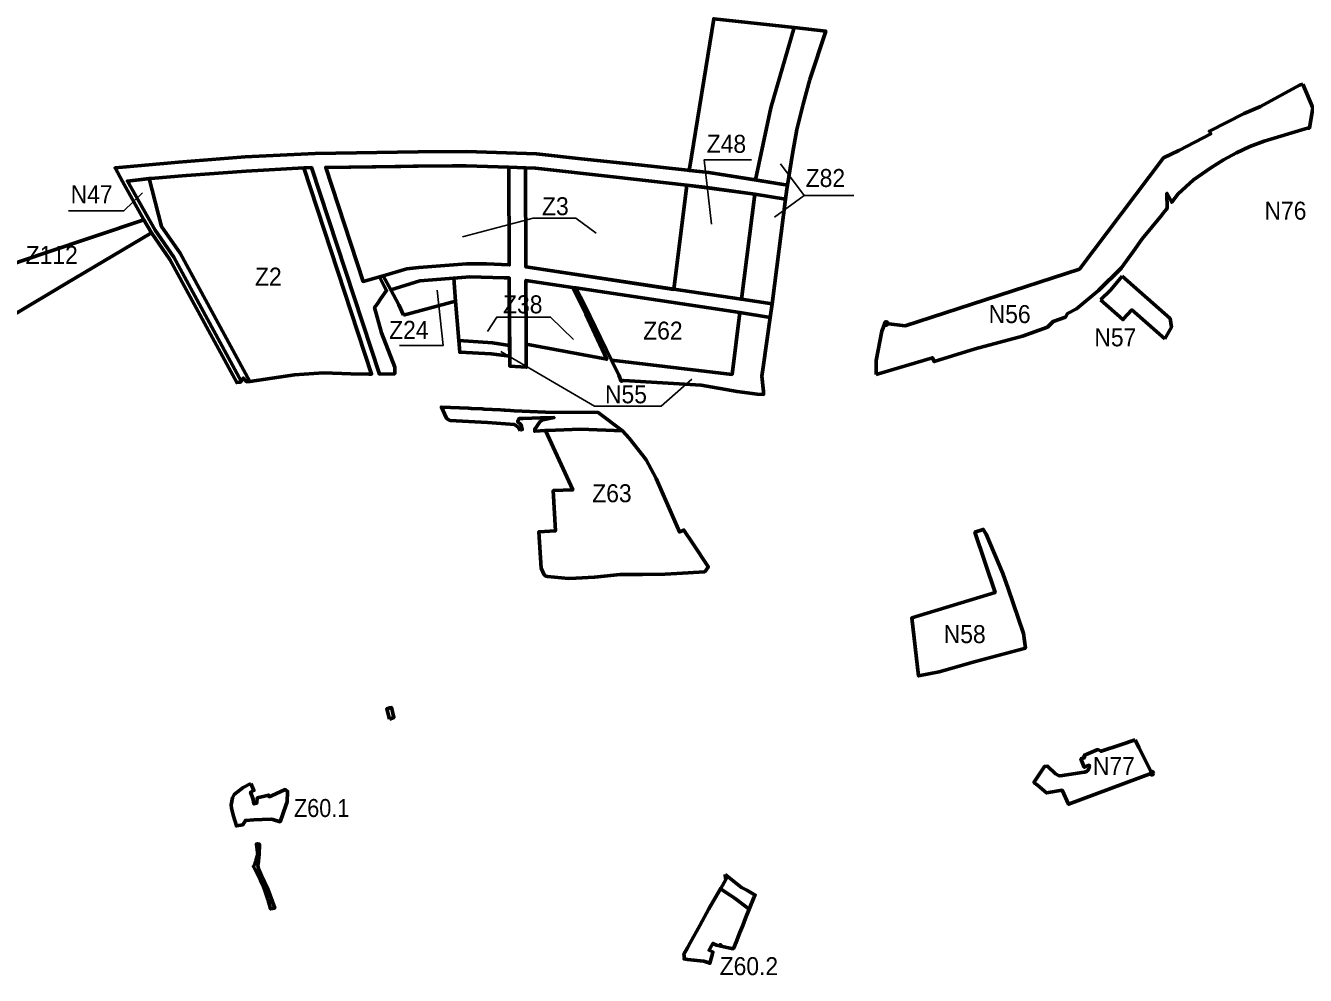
# Model space of a CAD drawing. Extents: x -650277 to -643422, y -1073980 to -1066720.
# Drawn here: x -647728 to -646020, y -1070629 to -1069362 of the extents above; entities that cross this region are included whole.
import ezdxf

# ---------------------------------------------------------------- set-up
doc = ezdxf.new("R2010")
doc.units = 0
doc.header["$LTSCALE"] = 9.6
doc.header["$PDMODE"] = 32
doc.header["$PDSIZE"] = 4.8
for name, color, linetype, lineweight in [('1', 7, 'Continuous', 60), ('13', 7, 'Continuous', 60), ('15', 7, 'Continuous', 60), ('17', 7, 'Continuous', 60), ('18', 7, 'Continuous', 60), ('35', 7, 'Continuous', 60), ('42', 7, 'Continuous', 60), ('48', 7, 'Continuous', 60), ('59', 7, 'Continuous', 25), ('60', 7, 'Continuous', 60), ('63', 7, 'Continuous', 25), ('9', 7, 'Continuous', 60)]:
    doc.layers.add(name, color=color, linetype=linetype, lineweight=lineweight)

msp = doc.modelspace()

# ---------------------------------------------------------------- linework, layer by layer
at = {"layer": '1'}
for points in [[(-647356.899, -1069552.034), (-647433.779, -1069556.106), (-647433.779, -1069556.106), (-647513.66, -1069562.249), (-647514.067, -1069562.282), (-647560.836, -1069566.036), (-647563.104, -1069566.28)], [(-647369.3, -1069828.22), (-647330.46, -1069825.51), (-647294.38, -1069826.88), (-647270.09, -1069827.02), (-647266.581, -1069827.042), (-647356.899, -1069552.034)], [(-647563.104, -1069566.28), (-647546.777, -1069629.901), (-647521.943, -1069665.763)], [(-647521.943, -1069665.763), (-647428.993, -1069836.714), (-647369.3, -1069828.22)]]:
    msp.add_lwpolyline(points, dxfattribs=at)
for points in [[(-647251.002, -1069695.852), (-647219.628, -1069686.746), (-647203.374, -1069684.716), (-647139.649, -1069679.961), (-647113.255, -1069679.966), (-647082.761, -1069681.399), (-647083.356, -1069551.018), (-647140.247, -1069549.071), (-647158.572, -1069549.252), (-647211.05, -1069549.77), (-647227.623, -1069550.23), (-647327.682, -1069551.263), (-647277.71, -1069703.421)], [(-646944.168, -1069563.743), (-647047.648, -1069552.245), (-647061.304, -1069551.773), (-647060.7, -1069683.894), (-646863, -1069714), (-646846, -1069575)], [(-647223.66, -1069748.26), (-647154.33, -1069729.69), (-647156.782, -1069698.901), (-647202.181, -1069702.678), (-647240.994, -1069714.513), (-647230.16, -1069734.42)], [(-647150.138, -1069782.334), (-647105.334, -1069785.168), (-647082.271, -1069788.81), (-647082.682, -1069698.791), (-647089.456, -1069698.579), (-647135.585, -1069697.137), (-647156.782, -1069698.901), (-647154.33, -1069729.69)], [(-647060.23, -1069786.932), (-646952.56, -1069807.13), (-646980.4, -1069746.98), (-646998.56, -1069711.443), (-647060.617, -1069702.116)]]:
    msp.add_lwpolyline(points, close=True, dxfattribs=at)
at = {"layer": '13'}
msp.add_line((-646733.74, -1069471.688), (-646702.425, -1069364.771), dxfattribs=at)
msp.add_lwpolyline([(-646702.425, -1069364.771), (-646809.879, -1069353.002), (-646842.103, -1069553.182), (-646842.441, -1069555.283), (-646816.615, -1069558.064), (-646754.066, -1069567.993), (-646733.74, -1069471.688)], dxfattribs=at)
msp.add_lwpolyline([(-646842.148, -1069716.763), (-646772.906, -1069727.176), (-646755.269, -1069587.04), (-646846, -1069575), (-646862.955, -1069713.634)], close=True, dxfattribs=at)
at = {"layer": '15'}
for points in [[(-647433.779, -1069556.106), (-647356.899, -1069552.034), (-647346.554, -1069551.486), (-647256.034, -1069827.107), (-647235.49, -1069826.51), (-647235.62, -1069817.62), (-647253.45, -1069771.95), (-647262.46, -1069738.25), (-647259.11, -1069733.52), (-647253.97, -1069726.27), (-647246.42, -1069715.63), (-647249.555, -1069709.677), (-647256.061, -1069697.32), (-647277.71, -1069703.421), (-647327.682, -1069551.263), (-647204.208, -1069549.647), (-647140.247, -1069549.071), (-647083.356, -1069551.018), (-647061.304, -1069551.773), (-647047.702, -1069552.239), (-646944.167, -1069563.743), (-646822.169, -1069577.72), (-646755.269, -1069587.04), (-646714.037, -1069593.585), (-646712.34, -1069580.49), (-646711.444, -1069574.771), (-646711.442, -1069574.759), (-646816.615, -1069558.064), (-646910.029, -1069548.006), (-646986.633, -1069539.757), (-647046.325, -1069533.275), (-647140.008, -1069530.068), (-647204.293, -1069530.647), (-647341.697, -1069532.602), (-647434.969, -1069537.141), (-647523.931, -1069544.499), (-647568.792, -1069548.21), (-647608.81, -1069551.868), (-647598.735, -1069570.026), (-647573.15, -1069616.16), (-647570.37, -1069621.18), (-647560.36, -1069638.39), (-647535.588, -1069674.163), (-647446.322, -1069838.338), (-647441.19, -1069837.6), (-647440.46, -1069836.558), (-647530.471, -1069671.013), (-647555.266, -1069635.207), (-647592.199, -1069569.411), (-647560.836, -1069566.036), (-647514.067, -1069562.282), (-647513.66, -1069562.249), (-647433.779, -1069556.106)], [(-647242.698, -1070287.238), (-647236.567, -1070285.154), (-647239.781, -1070272.031), (-647242.06, -1070272.35), (-647246.28, -1070273.733)], [(-647404.96, -1070527.57), (-647401.35, -1070540.59), (-647395.75, -1070539.47), (-647404.879, -1070514.114), (-647413.552, -1070496.671), (-647417.297, -1070487.185), (-647418.038, -1070482.516), (-647417.482, -1070476.846), (-647416.37, -1070468.064), (-647416.148, -1070454.055), (-647418.49, -1070453.76), (-647420.13, -1070454.78), (-647420.22, -1070454.02), (-647418.41, -1070468.21), (-647420.74, -1070476.57), (-647422.285, -1070480.931), (-647424.226, -1070484.029), (-647422.19, -1070487.75), (-647414.6, -1070502.16), (-647410.86, -1070510.68), (-647408.82, -1070515.49)]]:
    msp.add_lwpolyline(points, close=True, dxfattribs=at)
for points in [[(-647083.356, -1069551.018), (-647082.761, -1069681.399), (-647113.255, -1069679.966), (-647139.649, -1069679.961), (-647203.374, -1069684.716), (-647219.628, -1069686.746), (-647251.002, -1069695.852), (-647240.994, -1069714.513), (-647202.181, -1069702.678), (-647135.585, -1069697.137), (-647089.456, -1069698.579), (-647082.682, -1069698.791), (-647082.206, -1069802.916)], [(-647060.617, -1069702.116), (-646998.56, -1069711.443), (-646993.771, -1069712.163), (-646775.286, -1069745.022), (-646734.48, -1069751.35), (-646732.143, -1069733.308), (-646772.906, -1069727.176), (-646842.148, -1069716.763), (-647060.7, -1069683.894), (-647061.304, -1069551.773), (-647083.356, -1069551.018)], [(-647082.206, -1069802.916), (-647082.145, -1069816.321), (-647060.029, -1069817.854), (-647060.23, -1069786.932), (-647060.617, -1069702.116)], [(-646931.67, -1069902.89), (-646964.111, -1069878.315), (-647034.195, -1069877.629), (-647076, -1069875.85), (-647081.25, -1069875.56), (-647081.26, -1069875.76), (-647088.94, -1069875.34), (-647088.93, -1069875.14), (-647094.24, -1069874.85), (-647116.31, -1069873.65), (-647118.77, -1069873.51), (-647133.58, -1069872.73), (-647136.94, -1069872.55), (-647173.23, -1069871.09), (-647167.14, -1069884.85)], [(-647167.14, -1069884.85), (-647166.8, -1069885.63), (-647163.55, -1069887.98), (-647162.03, -1069888.89), (-647111.76, -1069891.77)], [(-647111.76, -1069891.77), (-647075.97, -1069894.33), (-647071, -1069897.87), (-647068.2, -1069902.28)], [(-647068.2, -1069902.28), (-647065.47, -1069901.09), (-647067.02, -1069894.68), (-647071.73, -1069890.39), (-647070.87, -1069888.71), (-647069.57, -1069886.35), (-647064.32, -1069886.23), (-647041.25, -1069885.62), (-647035.6, -1069885.43), (-647023.04, -1069885), (-647035.53, -1069887.44), (-647037.79, -1069887.88), (-647041.47, -1069890.42), (-647042.75, -1069892.14), (-647046.49, -1069897.19), (-647048.8, -1069900.51), (-647048.67, -1069903.32), (-647034.51, -1069902.21)], [(-647034.51, -1069902.21), (-647032.16, -1069902.13), (-646987.56, -1069900.52), (-646931.67, -1069902.89)], [(-646794.59, -1070494.62), (-646794.53, -1070495.7), (-646793.75, -1070501.26), (-646800.6, -1070513.43), (-646800.94, -1070514.04)], [(-646755.84, -1070524.5), (-646754.52, -1070522.08), (-646765.96, -1070515.75), (-646770.95, -1070512.94), (-646773, -1070511.96), (-646794.59, -1070494.62)], [(-646800.94, -1070514.04), (-646788, -1070522.49), (-646782.63, -1070526.02)], [(-646782.63, -1070526.02), (-646779.68, -1070527.87), (-646762.71, -1070540.85), (-646755.84, -1070524.5)]]:
    msp.add_lwpolyline(points, dxfattribs=at)
at = {"layer": '17'}
msp.add_lwpolyline([(-647427.8, -1070373.32), (-647437.76, -1070378.66), (-647449.69, -1070387.83), (-647452.17, -1070392.38), (-647453.71, -1070401.81), (-647453.35, -1070406.09), (-647450.51, -1070416.96), (-647446.93, -1070429.99), (-647438.45, -1070428.47), (-647434.85, -1070422.64), (-647423.38, -1070421.87), (-647412.51, -1070421.5), (-647400.41, -1070421.08), (-647398.21, -1070421.15), (-647388.6, -1070424.24), (-647381.11, -1070402.45), (-647379.3, -1070397.57), (-647378.49, -1070383.91), (-647381.65, -1070381.45), (-647400.22, -1070389.64), (-647403.27, -1070390.91), (-647404, -1070388.84), (-647409.36, -1070390.24), (-647419.08, -1070392.52), (-647419.68, -1070399.59), (-647423.58, -1070400.59), (-647424.54, -1070394.78), (-647425.99, -1070390.47), (-647427.96, -1070384.64), (-647423.57, -1070382.64)], close=True, dxfattribs=at)
msp.add_lwpolyline([(-647427.8, -1070373.32), (-647437.76, -1070378.66), (-647449.69, -1070387.83), (-647452.17, -1070392.38), (-647453.71, -1070401.81), (-647453.35, -1070406.09), (-647450.51, -1070416.96), (-647446.93, -1070429.99), (-647438.45, -1070428.47), (-647434.85, -1070422.64), (-647423.38, -1070421.87), (-647412.51, -1070421.5), (-647400.41, -1070421.08), (-647398.21, -1070421.15), (-647388.6, -1070424.24), (-647381.11, -1070402.45), (-647379.3, -1070397.57), (-647378.49, -1070383.91), (-647381.65, -1070381.45), (-647400.22, -1070389.64), (-647403.27, -1070390.91), (-647404, -1070388.84), (-647409.36, -1070390.24), (-647419.08, -1070392.52), (-647419.68, -1070399.59), (-647423.58, -1070400.59), (-647424.54, -1070394.78), (-647425.99, -1070390.47), (-647427.96, -1070384.64), (-647423.57, -1070382.64)], close=True, dxfattribs=at)
at = {"layer": '18'}
msp.add_lwpolyline([(-646785.437, -1069827.534), (-646775.286, -1069745.022), (-646993.771, -1069712.163), (-646981.92, -1069734.86), (-646946.369, -1069808.291)], close=True, dxfattribs=at)
at = {"layer": '35'}
msp.add_lwpolyline([(-647740.74, -1069744.24), (-647742.36, -1069746.93), (-647674.901, -1069706.701), (-647560.36, -1069638.39), (-647570.37, -1069621.18), (-647701.61, -1069665.279), (-647774.11, -1069689.64)], close=True, dxfattribs=at)
at = {"layer": '42'}
msp.add_line((-646230.3, -1069760.5), (-646208.135, -1069779.937), dxfattribs=at)
for points in [[(-646023.96, -1069440.34), (-646028.16, -1069441.58), (-646080.35, -1069469.89), (-646102.15, -1069479.49), (-646148.5, -1069503), (-646146.8, -1069506.6), (-646189.17, -1069528.74), (-646209.9, -1069538.5), (-646321.973, -1069686.855), (-646554.262, -1069762.602), (-646579.873, -1069759.61)], [(-646017.63, -1069499.08), (-646017.63, -1069499.08), (-646015.16, -1069498.74), (-646010.65, -1069471.91), (-646023.96, -1069440.34)], [(-646491.18, -1069802.78), (-646491.18, -1069802.78), (-646460.97, -1069793.56), (-646397.74, -1069776.29), (-646364.67, -1069764.23), (-646357, -1069756.7), (-646340.48, -1069750.92), (-646337.97, -1069746.4), (-646325.92, -1069740.05), (-646296.64, -1069715.72), (-646266.27, -1069685.75), (-646250, -1069663.09), (-646238.19, -1069646.63), (-646212.43, -1069615.33), (-646210.03, -1069612.42), (-646205.9, -1069607.17), (-646205, -1069606.03), (-646205.25, -1069585.67), (-646198.82, -1069597.83), (-646190.07, -1069586.48), (-646169.9, -1069568.04), (-646146.81, -1069551.97), (-646129.87, -1069541.19), (-646112.56, -1069531.78), (-646094.39, -1069523.34), (-646075.48, -1069516.38), (-646020.75, -1069500), (-646017.63, -1069499.08)], [(-646265.02, -1069696.43), (-646280.5, -1069715.27), (-646293.76, -1069728)], [(-646208.135, -1069779.937), (-646204.6, -1069773.78), (-646199.17, -1069764.33), (-646200.67, -1069752.88), (-646265.02, -1069696.43)], [(-646293.76, -1069728), (-646263.929, -1069754.309), (-646263.36, -1069753.69), (-646252.07, -1069741.41), (-646230.3, -1069760.5)], [(-646579.873, -1069759.61), (-646581.489, -1069759.421), (-646585.51, -1069769.57), (-646593.34, -1069808.99), (-646593.34, -1069827.68)], [(-647082.271, -1069788.81), (-647105.334, -1069785.168), (-647105.334, -1069785.168), (-647150.138, -1069782.334), (-647148.9, -1069797.88), (-647107.04, -1069799.84)], [(-647107.04, -1069799.84), (-647082.206, -1069802.916), (-647082.271, -1069788.81)], [(-646593.34, -1069827.68), (-646518.19, -1069805.27), (-646515.63, -1069810.24), (-646491.18, -1069802.78)]]:
    msp.add_lwpolyline(points, dxfattribs=at)
for points in [[(-647555.266, -1069635.207), (-647530.471, -1069671.013), (-647440.46, -1069836.558), (-647437.46, -1069832.27), (-647433.32, -1069837.33), (-647428.993, -1069836.714), (-647521.943, -1069665.763), (-647546.777, -1069629.901), (-647563.104, -1069566.28), (-647592.199, -1069569.411)], [(-646775.286, -1069745.022), (-646785.437, -1069827.534), (-646946.369, -1069808.291), (-646936.6, -1069828.47), (-646933.39, -1069836.51), (-646929.67, -1069835.68), (-646826.63, -1069841.84), (-646778.74, -1069850.44), (-646751.8, -1069853.72), (-646743.31, -1069854.26), (-646743.7, -1069850.07), (-646745.56, -1069829.84), (-646743.85, -1069817.72), (-646734.48, -1069751.35)]]:
    msp.add_lwpolyline(points, close=True, dxfattribs=at)
msp.add_point((-646579.873, -1069759.61), dxfattribs=at)
at = {"layer": '48'}
msp.add_point((-646225.15, -1070359.46), dxfattribs=at)
at = {"layer": '60'}
for points in [[(-646681.5, -1069434.17), (-646660.526, -1069369.36), (-646702.425, -1069364.771), (-646733.74, -1069471.688), (-646754.066, -1069567.993), (-646711.442, -1069574.759)], [(-646711.442, -1069574.759), (-646704.68, -1069533.06), (-646699.07, -1069500.57), (-646690.51, -1069466.97), (-646681.5, -1069434.17)]]:
    msp.add_lwpolyline(points, dxfattribs=at)
msp.add_lwpolyline([(-646755.269, -1069587.04), (-646772.906, -1069727.176), (-646732.143, -1069733.308), (-646725.82, -1069684.5), (-646714.037, -1069593.585)], close=True, dxfattribs=at)
at = {"layer": '63'}
msp.add_line((-646689.194, -1069588.733), (-646622.86, -1069588.733), dxfattribs=at)
for points in [[(-646759.573, -1069540.98), (-646822.671, -1069540.98), (-646813, -1069627)], [(-646720.743, -1069546.645), (-646689.194, -1069588.733), (-646728.832, -1069617.87)], [(-647671, -1069609), (-647597, -1069609), (-647572, -1069585)], [(-647145, -1069644), (-647051, -1069619), (-646994, -1069619), (-646967, -1069639)], [(-647229, -1069789), (-647171, -1069789), (-647179, -1069715)], [(-646997, -1069781), (-647027.656, -1069750.914), (-647099.524, -1069750.914), (-647112, -1069770)], [(-647094, -1069797), (-646969, -1069870), (-646880, -1069870), (-646839, -1069834)]]:
    msp.add_lwpolyline(points, dxfattribs=at)
at = {"layer": '9'}
for points in [[(-647032.16, -1069902.13), (-647034.51, -1069902.21), (-646998.06, -1069981.49), (-647024.05, -1069982.48), (-647021.27, -1070036.28), (-647043.25, -1070037.29), (-647040.12, -1070086.11), (-647036.03, -1070094.96), (-647034.17, -1070096.49), (-647031.73, -1070097.21), (-647003.49, -1070099.66), (-646993.92, -1070099.49), (-646968.89, -1070098.02), (-646934.63, -1070094.24), (-646904.97, -1070094.52), (-646874.9, -1070094.1), (-646859.29, -1070093.1), (-646821.89, -1070090.7), (-646817.15, -1070084.76), (-646816.9, -1070084.45), (-646837.65, -1070053.22), (-646849.79, -1070035.17), (-646855.62, -1070037.66), (-646886.85, -1069966.26), (-646900.26, -1069941.64), (-646904.72, -1069935.84), (-646922.79, -1069912.31), (-646931.67, -1069902.89), (-646987.56, -1069900.52)], [(-646247.667, -1070315.004), (-646267.3, -1070321.61), (-646293.14, -1070330.3), (-646297.4, -1070328.01), (-646315.84, -1070336.13), (-646314.84, -1070338.41), (-646319.95, -1070340.42), (-646315.46, -1070351.67), (-646308.791, -1070348.855), (-646308.59, -1070350.22), (-646309.18, -1070352.77), (-646309.99, -1070354.58), (-646311.82, -1070356.89), (-646314.6, -1070358.05), (-646315.7, -1070358.27), (-646347.49, -1070363.01), (-646349.76, -1070362.69), (-646353.81, -1070360.18), (-646364.34, -1070350.19), (-646368.4, -1070350.41), (-646382.67, -1070371.94), (-646377.86, -1070375.71), (-646365.7, -1070385.89), (-646344.93, -1070382.33), (-646336.35, -1070400.9), (-646225.15, -1070359.46), (-646242.56, -1070325.1)], [(-646802.19, -1070516.26), (-646816.42, -1070540.49), (-646828.45, -1070562.89), (-646841.16, -1070585.79), (-646844.76, -1070592.54), (-646849.72, -1070600.98), (-646848.99, -1070606.28), (-646849.59, -1070607.4), (-646844.96, -1070607.98), (-646827.88, -1070610.12), (-646822.99, -1070610.51), (-646815.05, -1070613.14), (-646812.5, -1070603.78), (-646811.5, -1070600.29), (-646810.82, -1070598.23), (-646816.11, -1070595.8), (-646814.52, -1070592.78), (-646811.06, -1070586.67), (-646806.41, -1070589), (-646802.06, -1070589.93), (-646801.73, -1070588.37), (-646800.13, -1070588.71), (-646800.47, -1070590.28), (-646784.18, -1070593.76), (-646784, -1070593.34), (-646783.59, -1070593.52), (-646779.9, -1070584.92), (-646774.91, -1070571.88), (-646771.17, -1070562.7), (-646767.63, -1070553.09), (-646762.71, -1070540.85), (-646782.63, -1070526.02), (-646788, -1070522.49), (-646800.94, -1070514.04)]]:
    msp.add_lwpolyline(points, close=True, dxfattribs=at)
for points in [[(-646417.23, -1070113.25), (-646424.17, -1070093.21), (-646446.21, -1070040.55), (-646450.22, -1070034.31), (-646461.415, -1070037.991), (-646434.503, -1070118.512), (-646545.78, -1070152.41), (-646536.47, -1070229.65), (-646509.31, -1070224.11), (-646460.8, -1070210.57)], [(-646460.8, -1070210.57), (-646393.97, -1070192.69), (-646396.51, -1070173.06), (-646417.23, -1070113.25)]]:
    msp.add_lwpolyline(points, dxfattribs=at)

# ---------------------------------------------------------------- texts
at = {"layer": '59', "width": 0.95}
msp.add_text('N76', height=24, dxfattribs=at).set_placement((-646075, -1069621))
at = {"layer": '63'}
for s, width, p in [('Z48', 0.95, (-646819.248, -1069531.795)), ('Z82', 0.95, (-646687.198, -1069577.402)), ('N47', 0.95, (-647668, -1069599)), ('Z3', 0.95, (-647039, -1069615)), ('Z112', 0.95, (-647728, -1069680)), ('Z2', 0.95, (-647422, -1069709)), ('Z38', 0.95, (-647091, -1069746)), ('N56', 0.95, (-646443, -1069759)), ('Z24', 0.95, (-647243, -1069780)), ('Z62', 0.95, (-646904, -1069781)), ('N57', 0.95, (-646302, -1069790)), ('N55', 0.95, (-646955, -1069866)), ('Z63', 0.95, (-646972, -1069998)), ('N58', 0.95, (-646503, -1070186)), ('N77', 0.95, (-646304, -1070362)), ('Z60.1', 0.9, (-647370, -1070418)), ('Z60.2', 0.95, (-646802, -1070629))]:
    msp.add_text(s, height=24, dxfattribs=dict(at, width=width)).set_placement(p)

doc.saveas('drawing.dxf')
